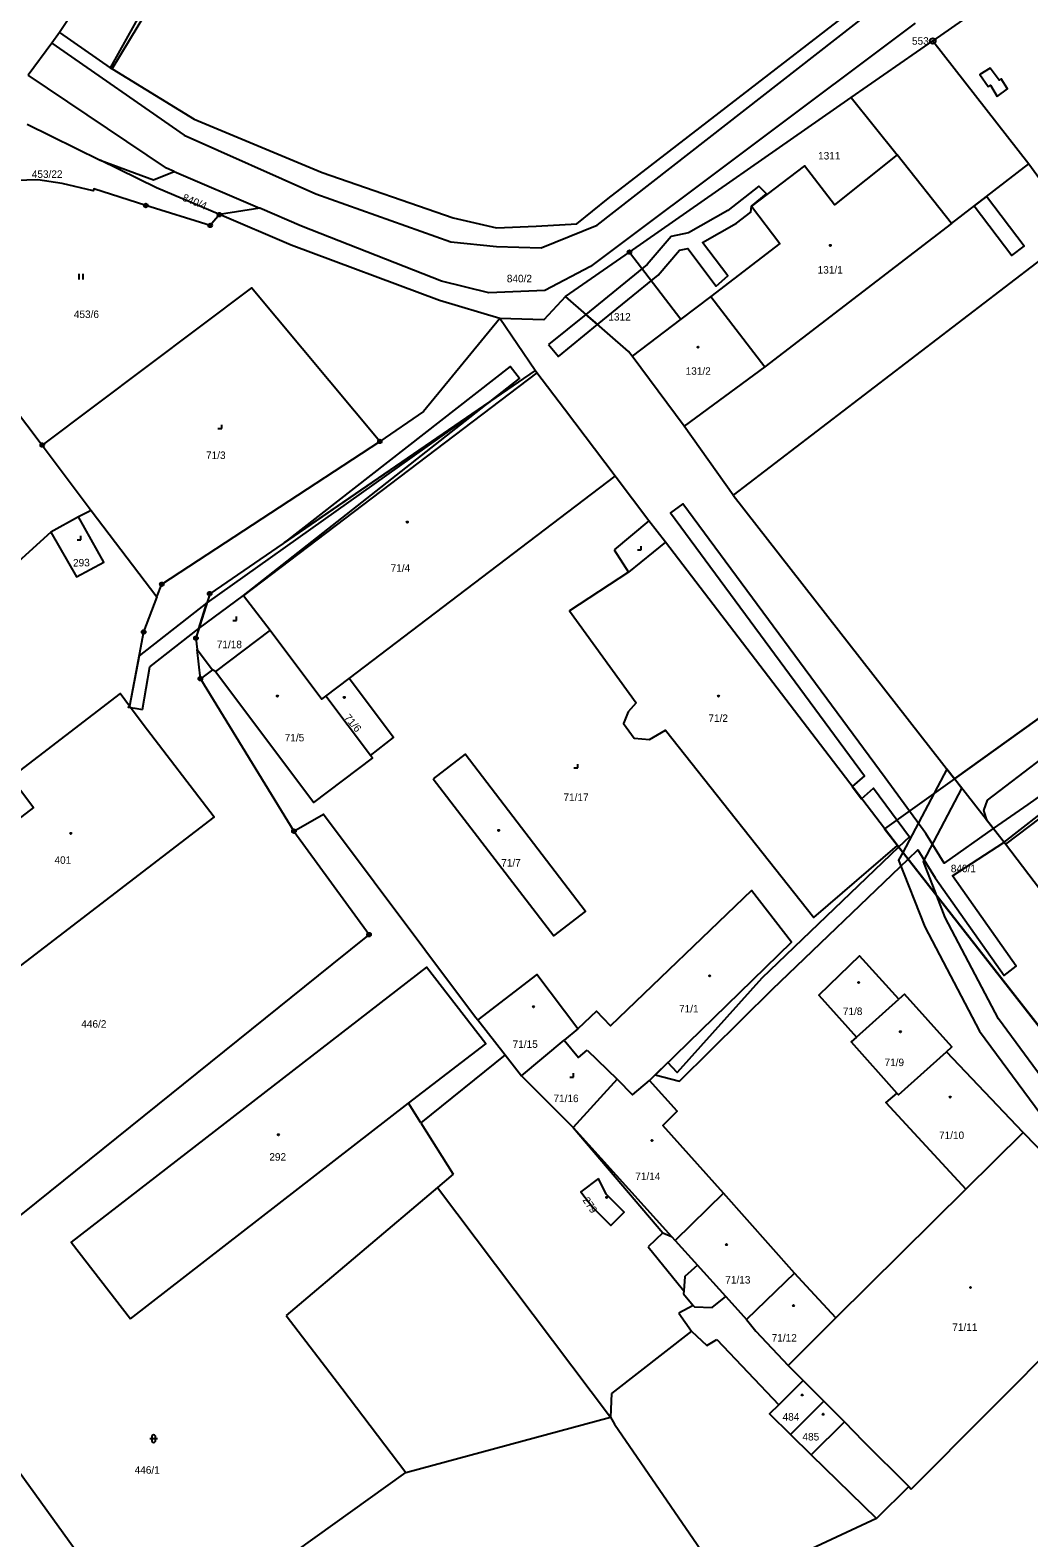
# Model space of a CAD drawing. Extents: x -745926 to -742978, y -968282 to -965689.
# Drawn here: x -745517.4 to -745384.4, y -966310.5 to -966109.7 of the extents above; entities that cross this region are included whole.
import ezdxf

# ---------------------------------------------------------------- set-up
doc = ezdxf.new("R2010")
doc.units = 0
for name, color, linetype in [('Hranice parcel', 7, 'Continuous'), ('Parcelní čísla', 7, 'Continuous'), ('Vnitřní kresba', 7, 'Continuous'), ('Věcná břemena k části', 7, 'Continuous'), ('Značky bodu BP', 7, 'Continuous'), ('Značky budov', 7, 'Continuous'), ('Značky kultur', 7, 'Continuous')]:
    doc.layers.add(name, color=color, linetype=linetype)

msp = doc.modelspace()

# ---------------------------------------------------------------- linework, layer by layer
at = {"layer": 'Hranice parcel'}
for p, q in [((-745408.06, -966118.66), (-745397.2, -966111.09)), ((-745437.59, -966139.25), (-745408.06, -966118.66)), ((-745408.06, -966118.66), (-745401.95, -966126.31)), ((-745517.85, -966122.22), (-745508.11, -966126.99)), ((-745492.21, -966134.26), (-745493.45, -966135.69)), ((-745446.1, -966145.18), (-745437.59, -966139.25)), ((-745437.59, -966139.25), (-745430.75, -966148.18)), ((-745426.77, -966145.14), (-745430.75, -966148.18)), ((-745528.74, -966147.93), (-745515.82, -966164.95)), ((-745450.15, -966155.02), (-745454.86, -966148.11)), ((-745430.75, -966148.18), (-745437.23, -966153.13)), ((-745430.31, -966162.42), (-745437.23, -966153.13)), ((-745450.15, -966155.02), (-745493.51, -966184.75)), ((-745449.94, -966155.31), (-745450.15, -966155.02)), ((-745423.78, -966171.61), (-745430.31, -966162.42)), ((-745499.9, -966183.49), (-745470.84, -966164.47)), ((-745515.82, -966164.95), (-745509.29, -966173.67)), ((-745474.95, -966196.07), (-745439.5, -966169.1)), ((-745423.78, -966171.61), (-745394.32, -966209.41)), ((-745509.29, -966173.67), (-745510.98, -966174.53)), ((-745509.29, -966173.67), (-745500.54, -966185.16)), ((-745510.98, -966174.53), (-745514.69, -966176.56)), ((-745401.9, -966218.3), (-745432.8, -966177.9)), ((-745500.54, -966185.16), (-745499.9, -966183.49)), ((-745485.47, -966189.61), (-745492.76, -966195.1)), ((-745495.18, -966192.2), (-745493.13, -966194.89)), ((-745492.76, -966195.1), (-745493.13, -966194.89)), ((-745478.04, -966198.39), (-745474.95, -966196.07)), ((-745472.08, -966206.3), (-745478.04, -966198.39)), ((-745387.49, -966218.13), (-745394.32, -966209.41)), ((-745376.94, -966210.06), (-745387.49, -966218.13)), ((-745482.29, -966216.39), (-745472.29, -966230.17)), ((-745355.31, -966277.88), (-745401.9, -966218.3)), ((-745380.56, -966227.22), (-745387.49, -966218.13)), ((-745407.37, -966243.85), (-745401.7, -966238.76)), ((-745444.46, -966242.71), (-745446.28, -966244.24)), ((-745451.96, -966249), (-745446.28, -966244.24)), ((-745443.22, -966245.56), (-745439.22, -966249.41)), ((-745385.13, -966256.52), (-745395.36, -966245.78)), ((-745439.22, -966249.41), (-745445.11, -966255.88)), ((-745392.8, -966264.1), (-745385.13, -966256.52)), ((-745425.09, -966264.62), (-745431.49, -966270.93)), ((-745415.6, -966275.27), (-745425.09, -966264.62)), ((-745392.8, -966264.1), (-745410.1, -966281.21)), ((-745415.6, -966275.27), (-745421.99, -966281.44)), ((-745410.1, -966281.21), (-745416.46, -966287.55)), ((-745416.46, -966287.55), (-745414.47, -966289.56)), ((-745414.47, -966289.56), (-745411.72, -966292.32)), ((-745416.16, -966296.75), (-745411.72, -966292.32)), ((-745411.72, -966292.32), (-745408.97, -966295.09)), ((-745400.39, -966303.71), (-745400.05, -966304.04))]:
    msp.add_line(p, q, dxfattribs=at)
for points in [[(-745461.97, -966022.68), (-745468.76, -966039.58), (-745477.16, -966056.16), (-745482.38, -966064.05), (-745493.85, -966079.07), (-745498.05, -966087.31), (-745501.9, -966092.6), (-745513.5, -966109.99)], [(-745506.51, -966114.85), (-745491.36, -966089.76), (-745479.8, -966070.63)], [(-745343.56, -966071.16), (-745343.39, -966073.57), (-745397.2, -966111.09)], [(-745506.51, -966114.85), (-745495.59, -966121.53), (-745478.55, -966128.66), (-745461.06, -966134.68), (-745455.31, -966136.03), (-745450.03, -966135.78), (-745444.6, -966135.5), (-745440.43, -966132.12), (-745436.33, -966128.95), (-745394.11, -966096.33)], [(-745513.5, -966109.99), (-745514.54, -966111.41), (-745517.68, -966115.69)], [(-745513.5, -966109.99), (-745506.79, -966114.68), (-745506.51, -966114.85)], [(-745397.2, -966111.09), (-745384.41, -966127.48), (-745377.88, -966136.44), (-745423.78, -966171.61)], [(-745401.95, -966126.31), (-745410.27, -966132.94), (-745414.27, -966127.74), (-745421.33, -966133.14), (-745417.56, -966138.11), (-745426.77, -966145.14)], [(-745508.11, -966126.99), (-745501.02, -966129.62), (-745498.23, -966128.5), (-745486.82, -966133.41), (-745492.21, -966134.26)], [(-745492.21, -966134.26), (-745500.59, -966130.67), (-745508.11, -966126.99)], [(-745493.45, -966135.69), (-745502.02, -966133.04), (-745508.96, -966130.81), (-745509.03, -966131.1), (-745513.15, -966130.13), (-745516.41, -966129.61), (-745519.36, -966129.69), (-745522.32, -966130.31)], [(-745454.86, -966148.11), (-745462.92, -966145.69), (-745482.68, -966138.33), (-745492.21, -966134.26)], [(-745470.84, -966164.47), (-745487.95, -966144.02), (-745515.82, -966164.95)], [(-745446.1, -966145.18), (-745449.02, -966148.27), (-745454.86, -966148.11)], [(-745437.23, -966153.13), (-745437.71, -966152.49), (-745446.1, -966145.18)], [(-745426.77, -966145.14), (-745419.56, -966154.55), (-745430.31, -966162.42)], [(-745454.86, -966148.11), (-745465.02, -966160.46), (-745470.84, -966164.47)], [(-745449.94, -966155.31), (-745489.02, -966184.98), (-745485.47, -966189.61)], [(-745439.5, -966169.1), (-745446.25, -966160.18), (-745449.94, -966155.31)], [(-745432.8, -966177.9), (-745435, -966175.05), (-745439.37, -966169.27), (-745439.5, -966169.1)], [(-745514.69, -966176.56), (-745511.24, -966182.52), (-745507.61, -966180.57), (-745510.98, -966174.53)], [(-745394.32, -966209.41), (-745347.72, -966176), (-745342.17, -966183.05)], [(-745514.69, -966176.56), (-745554.52, -966212.69), (-745570.61, -966191.39)], [(-745432.8, -966177.9), (-745437.71, -966181.87), (-745445.58, -966187.02), (-745436.69, -966199.29), (-745437.75, -966200.47), (-745438.41, -966202.06), (-745436.99, -966204), (-745434.91, -966204.19), (-745432.81, -966202.93), (-745413.04, -966227.89), (-745401.9, -966218.3)], [(-745500.54, -966185.16), (-745502.31, -966189.85), (-745504.21, -966199.72)], [(-745493.51, -966184.75), (-745495.34, -966190.68), (-745495.18, -966192.2)], [(-745485.47, -966189.61), (-745478.56, -966198.79), (-745478.04, -966198.39)], [(-745493.13, -966194.89), (-745494.76, -966196.08), (-745482.29, -966216.39)], [(-745492.76, -966195.1), (-745479.66, -966212.55), (-745471.81, -966206.66), (-745472.08, -966206.3)], [(-745472.08, -966206.3), (-745469.05, -966203.93), (-745474.95, -966196.07)], [(-745504.21, -966199.72), (-745505.45, -966198.07), (-745520.01, -966209.24), (-745518.82, -966210.81)], [(-745518.82, -966210.81), (-745516.99, -966213.24), (-745531.92, -966224.71), (-745522.38, -966237.14), (-745492.91, -966214.51), (-745502.37, -966202.17), (-745504.21, -966199.72)], [(-745463.74, -966209.43), (-745447.69, -966230.34), (-745443.47, -966227.11), (-745459.5, -966206.15), (-745463.74, -966209.43)], [(-745482.29, -966216.39), (-745478.34, -966214.12), (-745458.1, -966241.17), (-745457.81, -966241.54)], [(-745434.94, -966249.59), (-745416.02, -966231.18), (-745421.32, -966224.3), (-745440.13, -966242.32), (-745441.97, -966240.35), (-745444.46, -966242.71)], [(-745472.29, -966230.17), (-745477.24, -966234.15), (-745518.47, -966267.33), (-745519.21, -966267.92), (-745546.96, -966232.16)], [(-745504.05, -966281.36), (-745467.01, -966252.64), (-745456.73, -966244.72), (-745464.64, -966234.5), (-745511.96, -966271.15), (-745504.05, -966281.36)], [(-745401.7, -966238.76), (-745406.95, -966232.99), (-745412.39, -966238.24), (-745407.37, -966243.85)], [(-745444.46, -966242.71), (-745449.92, -966235.49), (-745457.81, -966241.54)], [(-745395.36, -966245.78), (-745394.65, -966245.14), (-745400.97, -966238.1), (-745401.7, -966238.76)], [(-745457.81, -966241.54), (-745454.16, -966246.17), (-745451.96, -966249)], [(-745446.28, -966244.24), (-745444.4, -966246.54), (-745443.22, -966245.56)], [(-745407.37, -966243.85), (-745408.07, -966244.46), (-745401.97, -966251.3)], [(-745401.97, -966251.3), (-745401.76, -966251.53), (-745395.36, -966245.78)], [(-745451.96, -966249), (-745445.32, -966255.64), (-745445.11, -966255.88)], [(-745439.22, -966249.41), (-745437.18, -966251.51), (-745434.94, -966249.59)], [(-745425.09, -966264.62), (-745433.17, -966255.6), (-745431.22, -966253.69), (-745434.94, -966249.59)], [(-745401.97, -966251.3), (-745403.45, -966252.54), (-745392.8, -966264.1)], [(-745445.11, -966255.88), (-745433.13, -966269.89), (-745431.98, -966270.39), (-745431.49, -966270.93)], [(-745400.05, -966304.04), (-745369.11, -966272.98), (-745385.13, -966256.52)], [(-745441.72, -966262.65), (-745444.07, -966264.45), (-745442.47, -966266.51), (-745440.1, -966268.9), (-745438.31, -966267.13), (-745440.69, -966264.74), (-745441.72, -966262.65)], [(-745431.49, -966270.93), (-745428.52, -966274.21), (-745430.2, -966275.73), (-745430.37, -966277.63), (-745430.41, -966278.04)], [(-745410.1, -966281.21), (-745414, -966277.02), (-745415.6, -966275.27)], [(-745430.41, -966278.04), (-745429.11, -966279.56), (-745428.95, -966279.74), (-745426.57, -966279.83)], [(-745426.57, -966279.83), (-745424.76, -966278.38), (-745421.99, -966281.44)], [(-745421.99, -966281.44), (-745420.77, -966283.01), (-745416.46, -966287.55)], [(-745414.47, -966289.56), (-745417.71, -966292.79), (-745418.95, -966294.02), (-745416.16, -966296.75)], [(-745478.86, -966358.72), (-745501.27, -966326.12), (-745467.37, -966301.81), (-745440.14, -966294.47), (-745439.57, -966295.38), (-745424.56, -966317.24)], [(-745416.16, -966296.75), (-745413.37, -966299.47), (-745408.97, -966295.09)], [(-745408.97, -966295.09), (-745406.46, -966297.64), (-745400.39, -966303.71)], [(-745400.39, -966303.71), (-745404.67, -966307.97), (-745424.56, -966317.24)]]:
    msp.add_lwpolyline(points, dxfattribs=at)
at = {"layer": 'Vnitřní kresba'}
for p, q in [((-745493.12, -966090.21), (-745506.79, -966114.68)), ((-745441.9, -966135.64), (-745393.24, -966097.7)), ((-745399.54, -966108.73), (-745442.8, -966141.18)), ((-745514.54, -966111.41), (-745496.9, -966123.68)), ((-745499.27, -966128.05), (-745517.68, -966115.69)), ((-745496.9, -966123.68), (-745479.39, -966131.49)), ((-745394.68, -966135.43), (-745401.95, -966126.31)), ((-745498.23, -966128.5), (-745499.27, -966128.05)), ((-745394.68, -966135.43), (-745384.41, -966127.48)), ((-745479.39, -966131.49), (-745461.38, -966137.88)), ((-745481.28, -966135.79), (-745486.82, -966133.41)), ((-745462.65, -966143.14), (-745481.28, -966135.79)), ((-745449.38, -966138.66), (-745441.9, -966135.64)), ((-745394.68, -966135.43), (-745419.56, -966154.55)), ((-745461.38, -966137.88), (-745455.3, -966138.51)), ((-745455.3, -966138.51), (-745449.38, -966138.66)), ((-745442.8, -966141.18), (-745448.89, -966144.35)), ((-745456.34, -966144.66), (-745462.65, -966143.14)), ((-745448.89, -966144.35), (-745456.34, -966144.66)), ((-745435, -966175.05), (-745439.63, -966178.93)), ((-745439.63, -966178.93), (-745437.71, -966181.87)), ((-745494.76, -966196.08), (-745495.18, -966192.2)), ((-745454.16, -966246.17), (-745465.37, -966255.25)), ((-745465.37, -966255.25), (-745467.01, -966252.64)), ((-745465.37, -966255.25), (-745461.09, -966262.08)), ((-745445.11, -966255.88), (-745431.98, -966270.39)), ((-745461.09, -966262.08), (-745463.19, -966263.87)), ((-745463.19, -966263.87), (-745483.33, -966280.92)), ((-745463.19, -966263.87), (-745440.14, -966294.47)), ((-745433.13, -966269.89), (-745435.11, -966271.77)), ((-745435.11, -966271.77), (-745430.54, -966277.42)), ((-745424.76, -966278.38), (-745428.52, -966274.21)), ((-745430.54, -966277.42), (-745430.37, -966277.63)), ((-745483.33, -966280.92), (-745475.93, -966290.61)), ((-745429.11, -966279.56), (-745431, -966280.6)), ((-745431, -966280.6), (-745429.33, -966283)), ((-745429.33, -966283), (-745440, -966291.3)), ((-745429.33, -966283), (-745427.27, -966284.9)), ((-745427.27, -966284.9), (-745425.98, -966284.11)), ((-745425.98, -966284.11), (-745417.71, -966292.79)), ((-745530.25, -966286.04), (-745501.27, -966326.12)), ((-745475.93, -966290.61), (-745467.37, -966301.81)), ((-745440, -966291.3), (-745440.14, -966294.47)), ((-745413.37, -966299.47), (-745404.67, -966307.97))]:
    msp.add_line(p, q, dxfattribs=at)
at = {"layer": 'Věcná břemena k části'}
for points in [[(-745388.63, -966118.51), (-745387.22, -966117.48), (-745388.1, -966116.17), (-745388.35, -966116.34), (-745389.54, -966114.74), (-745390.93, -966115.61), (-745389.82, -966117.17), (-745389.51, -966116.99)], [(-745433.78, -966142.32), (-745430.93, -966139.01), (-745429.81, -966138.78), (-745426.05, -966143.77), (-745424.51, -966142.42), (-745427.87, -966137.96), (-745423.36, -966135.41), (-745421.45, -966133.92), (-745421.33, -966133.14), (-745419.34, -966131.47), (-745420.35, -966130.47), (-745424.5, -966133.71), (-745429.74, -966136.68), (-745432.03, -966137.15), (-745435.26, -966140.92), (-745443.4, -966147.54), (-745441.84, -966148.89)], [(-745391.67, -966133.1), (-745386.65, -966139.7), (-745385.03, -966138.46), (-745390.05, -966131.85)], [(-745448.36, -966151.57), (-745447.07, -966153.15), (-745441.84, -966148.89), (-745443.4, -966147.54)], [(-745483.55, -966177.92), (-745456.17, -966159.15), (-745452.25, -966156.09), (-745453.51, -966154.49)], [(-745489.02, -966184.98), (-745456.17, -966159.15), (-745493.89, -966185.99), (-745494.94, -966189.39)], [(-745389.89, -966212.25), (-745353.25, -966184.28), (-745345.6, -966178.69), (-745342.17, -966183.05), (-745338.46, -966187.93), (-745338.27, -966187.79), (-745333.03, -966194.69), (-745333.21, -966194.83), (-745329.47, -966199.75), (-745339.63, -966207.3), (-745345.08, -966200.09), (-745353.55, -966206.54), (-745349.68, -966211.58), (-745356.71, -966216.98), (-745360.49, -966211.82), (-745369.95, -966219.08), (-745380.56, -966227.22), (-745387.49, -966218.13), (-745389.95, -966214.99), (-745390.37, -966213.63)], [(-745502.47, -966200.19), (-745501.47, -966194.48), (-745494.94, -966189.39), (-745493.89, -966185.99), (-745502.92, -966193.03), (-745504.21, -966199.72), (-745504.38, -966199.85), (-745503.47, -966200.01)]]:
    msp.add_lwpolyline(points, close=True, dxfattribs=at)
for points in [[(-745374.99, -966206.07), (-745384.55, -966212.82), (-745389.15, -966216.05), (-745395.69, -966220.64), (-745398.11, -966216.68), (-745403.54, -966209.28), (-745430.47, -966172.78), (-745432.11, -966174), (-745406.28, -966209), (-745407.91, -966210.44), (-745406.67, -966212.07), (-745405.07, -966210.65), (-745400.31, -966217.13), (-745401.74, -966218.5), (-745419.98, -966235.99), (-745431.26, -966248.55), (-745432.47, -966247.19), (-745434.19, -966248.86), (-745430.95, -966249.68), (-745418.56, -966237.45), (-745400.48, -966220.12), (-745399.17, -966218.86), (-745396.86, -966222.62), (-745387.69, -966235.6), (-745386.07, -966234.36), (-745394.56, -966222.34), (-745387.71, -966217.9), (-745373.6, -966206.9)], [(-745347.72, -966176), (-745394.32, -966209.41), (-745403.61, -966216.07), (-745401.9, -966218.3), (-745355.31, -966277.88)], [(-745380.38, -966252.3), (-745388.42, -966241.41), (-745395.53, -966227.89), (-745396.66, -966225), (-745398.44, -966220.43), (-745393.3, -966210.72), (-745394.32, -966209.41), (-745395.32, -966208.13), (-745401.19, -966219.21), (-745401.74, -966220.25), (-745398.27, -966229.13), (-745390.96, -966243.01), (-745382.78, -966254.1)]]:
    msp.add_lwpolyline(points, dxfattribs=at)
at = {"layer": 'Značky bodu BP'}
for centre, radius in [((-745397.19, -966111.12), 0.375), ((-745397.19, -966111.12), 0.015), ((-745502.02, -966133.04), 0.25), ((-745502.02, -966133.04), 0.0152), ((-745492.21, -966134.26), 0.25), ((-745492.21, -966134.26), 0.0152), ((-745493.45, -966135.69), 0.25), ((-745493.45, -966135.69), 0.0152), ((-745437.59, -966139.25), 0.25), ((-745437.59, -966139.25), 0.0152), ((-745470.84, -966164.47), 0.25), ((-745470.84, -966164.47), 0.0152), ((-745515.82, -966164.95), 0.25), ((-745515.82, -966164.95), 0.0152), ((-745499.9, -966183.49), 0.25), ((-745499.9, -966183.49), 0.0152), ((-745493.51, -966184.75), 0.25), ((-745493.51, -966184.75), 0.0152), ((-745502.31, -966189.85), 0.25), ((-745502.31, -966189.85), 0.0152), ((-745495.34, -966190.68), 0.25), ((-745495.34, -966190.68), 0.0152), ((-745494.76, -966196.08), 0.25), ((-745494.76, -966196.08), 0.0152), ((-745482.29, -966216.39), 0.25), ((-745482.29, -966216.39), 0.0152), ((-745472.29, -966230.17), 0.25), ((-745472.29, -966230.17), 0.0152)]:
    msp.add_circle(centre, radius, dxfattribs=at)
at = {"layer": 'Značky budov'}
for centre in [(-745410.84, -966138.35), (-745428.45, -966151.91), (-745467.19, -966175.21), (-745484.5, -966198.39), (-745475.59, -966198.57), (-745425.74, -966198.39), (-745512.01, -966216.68), (-745455.02, -966216.28), (-745426.9, -966235.66), (-745407.05, -966236.55), (-745450.38, -966239.77), (-745401.5, -966243.11), (-745394.88, -966251.81), (-745484.36, -966256.83), (-745434.61, -966257.6), (-745440.63, -966265.18), (-745424.67, -966271.46), (-745392.17, -966277.18), (-745415.75, -966279.59), (-745414.59, -966291.5), (-745411.79, -966294.07)]:
    msp.add_circle(centre, 0.0875, dxfattribs=at)
at = {"layer": 'Značky kultur'}
for p, q in [((-745510.89, -966142.91), (-745510.89, -966142.16)), ((-745510.39, -966142.91), (-745510.39, -966142.16)), ((-745491.91, -966162.74), (-745491.91, -966162.24)), ((-745492.41, -966162.74), (-745491.91, -966162.74)), ((-745511.17, -966177.56), (-745510.67, -966177.56)), ((-745510.67, -966177.56), (-745510.67, -966177.06)), ((-745436.04, -966178.92), (-745436.04, -966178.42)), ((-745436.54, -966178.92), (-745436.04, -966178.92)), ((-745490.45, -966188.31), (-745489.95, -966188.31)), ((-745489.95, -966188.31), (-745489.95, -966187.81)), ((-745444.99, -966207.95), (-745444.49, -966207.95)), ((-745444.49, -966207.95), (-745444.49, -966207.45)), ((-745445.04, -966249.14), (-745445.04, -966248.64)), ((-745445.54, -966249.14), (-745445.04, -966249.14)), ((-745501.48, -966297.31), (-745500.48, -966297.31)), ((-745501.23, -966297.06), (-745501.23, -966297.56)), ((-745500.73, -966297.56), (-745500.73, -966297.06))]:
    msp.add_line(p, q, dxfattribs=at)
for centre, start, end in [((-745500.98, -966297.06), 0, 180), ((-745500.98, -966297.56), 180, 359.9879)]:
    msp.add_arc(centre, 0.25, start, end, dxfattribs=at)

# ---------------------------------------------------------------- texts
at = {"layer": 'Parcelní čísla'}
for s, p in [('1311', (-745412.47, -966126.91)), ('453/22', (-745517.21, -966129.36)), ('840/2', (-745453.93, -966143.27)), ('131/1', (-745412.53, -966142.11)), ('453/6', (-745511.61, -966148.03)), ('1312', (-745440.41, -966148.37)), ('131/2', (-745430.11, -966155.59)), ('71/3', (-745494, -966166.81)), ('71/4', (-745469.41, -966181.83)), ('71/18', (-745492.57, -966192.01)), ('71/2', (-745427.08, -966201.84)), ('71/5', (-745483.52, -966204.43)), ('71/17', (-745446.39, -966212.37)), ('401', (-745514.19, -966220.74)), ('71/7', (-745454.68, -966221.1)), ('840/1', (-745394.79, -966221.86)), ('71/1', (-745430.99, -966240.54)), ('71/8', (-745409.17, -966240.88)), ('446/2', (-745510.62, -966242.57)), ('71/15', (-745453.16, -966245.26)), ('71/9', (-745403.62, -966247.69)), ('71/16', (-745447.72, -966252.49)), ('71/10', (-745396.36, -966257.4)), ('292', (-745485.57, -966260.28)), ('71/14', (-745436.82, -966262.86)), ('71/13', (-745424.83, -966276.65)), ('71/11', (-745394.59, -966282.97)), ('71/12', (-745418.65, -966284.38)), ('484', (-745417.2, -966294.91)), ('485', (-745414.55, -966297.56)), ('446/1', (-745503.51, -966301.99))]:
    msp.add_text(s, height=1, dxfattribs=at).set_placement(p)
for s, rotation, p in [('840/4', 338, (-745497.24, -966132.36)), ('293', 1, (-745511.71, -966181.14)), ('71/6', 310, (-745475.66, -966201.31)), ('279', 304, (-745443.89, -966265.55))]:
    msp.add_text(s, height=1, rotation=rotation, dxfattribs=at).set_placement(p)
at = {"layer": 'Značky bodu BP'}
msp.add_text('553', height=1, dxfattribs=at).set_placement((-745399.96, -966111.62))

doc.saveas('drawing.dxf')
